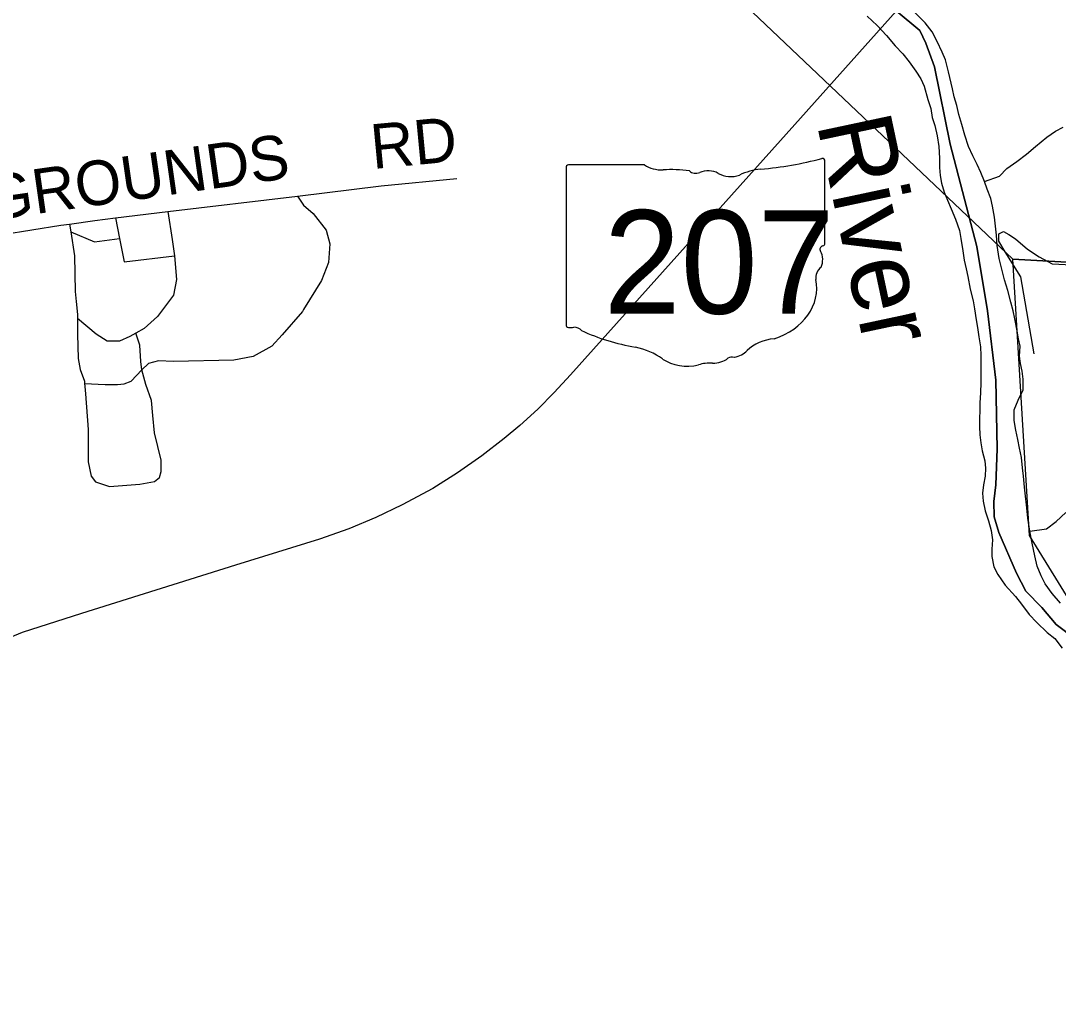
# Model space of a CAD drawing. Extents: x 0 to 34, y 0 to 22.
# Drawn here: x 3.839 to 5.16, y 18.553 to 19.8 of the extents above; entities that cross this region are included whole.
import ezdxf

# ---------------------------------------------------------------- set-up
doc = ezdxf.new("R2010")
doc.units = 0
for name, color, linetype in [('GM_X_Corporation', 7, 'Continuous'), ('GM_X_County_Road', 7, 'Continuous'), ('GM_X_County_Road_Text', 7, 'Continuous'), ('GM_X_Major_River', 7, 'Continuous'), ('GM_X_Major_River_Text', 7, 'Continuous'), ('GM_X_Minor_River', 7, 'Continuous'), ('GM_X_State_Location', 7, 'Continuous'), ('GM_X_State_Route', 7, 'Continuous'), ('GM_X_State_Shield', 7, 'Continuous'), ('GM_X_Township_Road', 7, 'Continuous'), ('SH_Data', 7, 'Continuous')]:
    doc.layers.add(name, color=color, linetype=linetype)

msp = doc.modelspace()

# ---------------------------------------------------------------- linework, layer by layer
at = {"layer": 'GM_X_Corporation'}
for points in [[(4.8161, 20.4698), (5.8125, 20.4147), (5.7537, 19.4608), (5.102, 19.4969), (4.7709, 19.8114)], [(5.102, 19.4969), (5.7537, 19.4608), (5.6796, 18.4816), (5.1903, 18.5084), (5.3139, 18.6644), (5.3147, 18.8352), (5.3148, 18.8557), (5.2004, 19.0195), (5.1234, 19.1449)]]:
    msp.add_lwpolyline(points, close=True, dxfattribs=at)
for points in [[(5.1813, 19.0133), (5.1572, 19.0317), (5.1391, 19.0531), (5.1188, 19.0738), (5.1068, 19.0967), (5.0844, 19.1486), (5.0785, 19.1684), (5.0779, 19.1882), (5.0804, 19.2095), (5.0822, 19.2551), (5.0807, 19.3425), (5.07, 19.4308), (5.0562, 19.513), (5.0223, 19.6432), (5.0025, 19.7419), (4.9914, 19.7718), (4.9836, 19.7878), (4.9535, 19.8132)], [(4.9535, 19.8132), (4.9836, 19.7878), (4.9914, 19.7718), (5.0025, 19.7419), (5.0223, 19.6432), (5.0562, 19.513), (5.07, 19.4308), (5.0807, 19.3425), (5.0822, 19.2551), (5.0804, 19.2095), (5.0779, 19.1882), (5.0785, 19.1684), (5.0844, 19.1486), (5.1068, 19.0967), (5.1188, 19.0738), (5.1391, 19.0531), (5.1572, 19.0317), (5.1813, 19.0133)]]:
    msp.add_lwpolyline(points, dxfattribs=at)
at = {"layer": 'GM_X_County_Road'}
for points in [[(4.1914, 19.5772), (4.2981, 19.5901), (4.3942, 19.5993)], [(3.5575, 19.4864), (3.89, 19.5399), (3.9012, 19.5415), (3.9335, 19.5461), (3.9596, 19.5492), (4.0263, 19.5573), (4.1914, 19.5772)], [(4.1914, 19.5772), (4.199, 19.5656), (4.2114, 19.5549), (4.2281, 19.5336), (4.2326, 19.5163), (4.2309, 19.4927), (4.2222, 19.4698), (4.1993, 19.4327)], [(4.0263, 19.5573), (4.0317, 19.5219), (4.0348, 19.5011), (4.0376, 19.4709), (4.0337, 19.4511), (4.0133, 19.4239), (3.9961, 19.4085), (3.9856, 19.4025), (3.9781, 19.3982), (3.9648, 19.3923), (3.9491, 19.3923), (3.935, 19.4011), (3.9115, 19.4212)], [(3.9596, 19.5492), (3.9647, 19.5231), (3.9706, 19.4934), (4.0348, 19.5011)], [(3.9012, 19.5415), (3.9027, 19.5317), (3.9076, 19.5011), (3.9084, 19.4555), (3.9097, 19.4428)], [(3.9027, 19.5317), (3.9329, 19.5188), (3.9647, 19.5231)], [(3.9097, 19.4428), (3.9115, 19.4261), (3.9115, 19.4212), (3.9115, 19.4011), (3.9123, 19.3703), (3.9146, 19.3563), (3.9201, 19.3416), (3.9204, 19.3386), (3.9208, 19.3348)], [(4.1993, 19.4327), (4.1987, 19.4319), (4.1977, 19.4302), (4.1718, 19.4005), (4.1588, 19.3858), (4.1349, 19.3728), (4.1103, 19.3681), (4.0335, 19.3665), (4.0145, 19.3672), (4.0017, 19.3639), (3.9931, 19.3558)], [(3.9208, 19.3348), (3.9217, 19.3254), (3.9248, 19.2799), (3.9248, 19.2387), (3.9287, 19.2204), (3.9342, 19.213), (3.9522, 19.2071), (3.9906, 19.2101), (4.0094, 19.2137), (4.0157, 19.2189), (4.018, 19.2262), (4.018, 19.2409), (4.0094, 19.2755), (4.0071, 19.2975), (4.0055, 19.3166), (3.9985, 19.3372), (3.9931, 19.3558), (3.9922, 19.3666), (3.9906, 19.3872), (3.9856, 19.4025)], [(3.9204, 19.3386), (3.9467, 19.3372), (3.9624, 19.3372), (3.971, 19.3379), (3.9797, 19.3416), (3.9931, 19.3558)]]:
    msp.add_lwpolyline(points, dxfattribs=at)
at = {"layer": 'GM_X_Major_River'}
for points in [[(4.9165, 19.8064), (4.9294, 19.7942), (4.9412, 19.7817), (4.9522, 19.7684), (4.962, 19.7581), (4.97, 19.7482), (4.9787, 19.736), (4.9851, 19.7265), (4.9893, 19.717), (4.9938, 19.6999), (4.9976, 19.6885), (4.9995, 19.6771), (5.0029, 19.6668), (5.0059, 19.6539), (5.0078, 19.6402), (5.0089, 19.6254), (5.0089, 19.6136), (5.0096, 19.6033), (5.0115, 19.5934), (5.0149, 19.582), (5.0191, 19.5718), (5.0236, 19.5607), (5.0293, 19.5478), (5.0342, 19.5334), (5.0361, 19.5231), (5.0383, 19.5075), (5.0402, 19.4953), (5.0428, 19.4843), (5.0447, 19.4748), (5.0477, 19.4585), (5.0515, 19.4436), (5.0534, 19.4334), (5.0556, 19.4197), (5.0572, 19.4098), (5.059, 19.3977), (5.0609, 19.3851), (5.0613, 19.3741), (5.0616, 19.3634), (5.0616, 19.3509), (5.0612, 19.3395), (5.0608, 19.3266), (5.06, 19.3137)], [(5.114, 19.3542), (5.1118, 19.3637), (5.1106, 19.3732), (5.1114, 19.3858), (5.1095, 19.3953), (5.1077, 19.4055), (5.1046, 19.4208), (5.1024, 19.431), (5.0997, 19.442), (5.0956, 19.4569), (5.0914, 19.4706), (5.088, 19.4839), (5.0846, 19.4975), (5.0824, 19.5143), (5.0813, 19.5272), (5.0802, 19.5386), (5.0787, 19.5504), (5.0764, 19.5641), (5.0741, 19.5739), (5.0696, 19.5861), (5.0662, 19.5956), (5.0613, 19.607), (5.0567, 19.6173), (5.0514, 19.6283), (5.0458, 19.6401), (5.0409, 19.6546), (5.0371, 19.6683), (5.0333, 19.6808), (5.0307, 19.6926), (5.0276, 19.7036), (5.0254, 19.7135), (5.0201, 19.7355), (5.0163, 19.7508), (5.0122, 19.7603), (5.0057, 19.774), (4.9993, 19.7865), (4.9906, 19.7979), (4.9766, 19.8116)], [(5.1629, 19.0585), (5.1523, 19.0711), (5.1432, 19.0832), (5.1383, 19.0935), (5.133, 19.1057), (5.13, 19.119), (5.1269, 19.1349), (5.1239, 19.1502), (5.1213, 19.1669), (5.1194, 19.184), (5.1183, 19.195), (5.1168, 19.2064), (5.1157, 19.2205), (5.1146, 19.2311), (5.1131, 19.244), (5.1108, 19.2562), (5.1086, 19.2672), (5.1059, 19.279), (5.104, 19.2912), (5.1037, 19.3049), (5.109, 19.3174), (5.1155, 19.3303), (5.1155, 19.344), (5.114, 19.3542)], [(5.06, 19.3137), (5.06, 19.3042), (5.0596, 19.2939), (5.0596, 19.2836), (5.06, 19.273), (5.0615, 19.2627), (5.0633, 19.2525), (5.0664, 19.2399), (5.0675, 19.2304), (5.0671, 19.2206), (5.0648, 19.2092), (5.0636, 19.1989), (5.0644, 19.1886), (5.067, 19.1761), (5.0712, 19.1635), (5.0746, 19.1514), (5.0764, 19.1392), (5.0753, 19.1274), (5.0753, 19.1179), (5.0779, 19.105), (5.0832, 19.0951), (5.0923, 19.0814), (5.1056, 19.067), (5.1131, 19.0574), (5.123, 19.0441), (5.1325, 19.0339), (5.1457, 19.0213), (5.1556, 19.0137), (5.1651, 19.0015)]]:
    msp.add_lwpolyline(points, dxfattribs=at)
at = {"layer": 'GM_X_Minor_River'}
for points in [[(5.0662, 19.5956), (5.0852, 19.6024), (5.0943, 19.6123), (5.1073, 19.621), (5.1194, 19.6305), (5.1312, 19.6404), (5.1453, 19.6521), (5.1563, 19.6597), (5.1662, 19.665)], [(5.1239, 19.1502), (5.1448, 19.1535), (5.1574, 19.1626), (5.1695, 19.174)]]:
    msp.add_lwpolyline(points, dxfattribs=at)
at = {"layer": 'GM_X_State_Route'}
for points in [[(4.9843, 19.8469), (4.9537, 19.8127), (4.8244, 19.6683)], [(4.8244, 19.6683), (4.5392, 19.3496), (4.5182, 19.3268), (4.4976, 19.3059), (4.4745, 19.2848), (4.4544, 19.2684), (4.4263, 19.2464), (4.3952, 19.2247), (4.3638, 19.2049), (4.3247, 19.1837), (4.2913, 19.1678), (4.2568, 19.1533), (4.2195, 19.1403), (4.1126, 19.1069), (3.9165, 19.0455), (3.8411, 19.0212), (3.7999, 19.0044), (3.7716, 18.9862), (3.7568, 18.9738)]]:
    msp.add_lwpolyline(points, dxfattribs=at)
at = {"layer": 'GM_X_State_Shield'}
for p, q in [((4.6331, 19.6167), (4.5366, 19.6167)), ((4.863, 19.517), (4.863, 19.6217)), ((4.5334, 19.6133), (4.5334, 19.4132)), ((4.8629, 19.517), (4.863, 19.517))]:
    msp.add_line(p, q, dxfattribs=at)
for centre, major_axis, start_param, end_param in [((4.5371, 19.6137), (0.00382, 0), 1.712693, 3.28349), ((4.6561, 19.64), (0.037, 0), 4.042523, 4.731795), ((4.7456, 19.8896), (0.3495, 0), 4.814394, 5.042369), ((4.8593, 19.6221), (0.00367, 0), 6.141152, 7.989035), ((4.6684, 19.5044), (0.133, 0), 1.404758, 1.657858), ((4.6986, 19.6147), (0.0107, 0), 3.836095, 5.185415), ((4.7143, 19.5916), (0.0222, 0), 0.950623, 2.079405), ((4.7429, 19.6233), (0.0267, 0), 4.081561, 5.145723), ((4.7901, 19.5556), (0.0703, 0), 1.699011, 2.107814), ((4.8621, 19.5093), (0.00568, 0), 1.883978, 3.671073), ((4.859, 19.5166), (0.00393, 0), 5.05454, 6.418171), ((4.826, 19.4961), (0.0341, 0), 5.934695, 6.695948), ((4.8761, 19.4732), (0.0248, 0), 2.387724, 3.262537), ((4.7651, 19.4599), (0.0874, 0), 5.101752, 6.440018), ((4.5372, 19.4127), (0.00385, 0), 3.00124, 4.508301), ((4.5378, 19.4332), (0.0294, 0), 4.665946, 4.897461), ((4.5438, 19.4016), (0.0106, 0), 0.519207, 1.627899), ((4.6776, 19.5814), (0.2524, 0), 4.195997, 4.488961), ((4.802, 19.357), (0.0479, 0), 1.647645, 2.488434), ((4.6024, 19.3233), (0.079, 0), 0.823519, 1.323587), ((4.7413, 19.3938), (0.0282, 0), 4.937069, 5.64225), ((4.6878, 19.4006), (0.0501, 0), 4.026481, 4.996735), ((4.7167, 19.3314), (0.0412, 0), 1.495662, 1.94098), ((4.7204, 19.3856), (0.0267, 0), 4.691044, 5.507374), ((4.7445, 19.3662), (0.00752, 0), 1.147584, 2.315152)]:
    msp.add_ellipse(centre, major_axis=major_axis, ratio=0.8, start_param=start_param, end_param=end_param, dxfattribs=at)
at = {"layer": 'GM_X_Township_Road'}
for points in [[(5.1295, 19.3763), (5.1124, 19.4743), (5.0923, 19.5061), (5.0844, 19.5199), (5.0842, 19.5289), (5.0902, 19.532), (5.0969, 19.5282)], [(5.0969, 19.5282), (5.1057, 19.5228), (5.1208, 19.5094), (5.1358, 19.4998), (5.1521, 19.491), (5.2023, 19.4881), (5.4979, 19.4701)]]:
    msp.add_lwpolyline(points, dxfattribs=at)
at = {"layer": 'SH_Data'}
for p, q in [((4.6331, 19.6167), (4.5366, 19.6167)), ((4.863, 19.517), (4.863, 19.6217)), ((4.5334, 19.6133), (4.5334, 19.4132)), ((4.8629, 19.517), (4.863, 19.517))]:
    msp.add_line(p, q, dxfattribs=at)
for centre, major_axis, start_param, end_param in [((4.5371, 19.6137), (0.00382, 0), 1.712693, 3.28349), ((4.6561, 19.64), (0.037, 0), 4.042523, 4.731795), ((4.7456, 19.8896), (0.3495, 0), 4.814394, 5.042369), ((4.8593, 19.6221), (0.00367, 0), 6.141152, 7.989035), ((4.6684, 19.5044), (0.133, 0), 1.404758, 1.657858), ((4.6986, 19.6147), (0.0107, 0), 3.836095, 5.185415), ((4.7143, 19.5916), (0.0222, 0), 0.950623, 2.079405), ((4.7429, 19.6233), (0.0267, 0), 4.081561, 5.145723), ((4.7901, 19.5556), (0.0703, 0), 1.699011, 2.107814), ((4.8621, 19.5093), (0.00568, 0), 1.883978, 3.671073), ((4.859, 19.5166), (0.00393, 0), 5.05454, 6.418171), ((4.826, 19.4961), (0.0341, 0), 5.934695, 6.695948), ((4.8761, 19.4732), (0.0248, 0), 2.387724, 3.262537), ((4.7651, 19.4599), (0.0874, 0), 5.101752, 6.440018), ((4.5372, 19.4127), (0.00385, 0), 3.00124, 4.508301), ((4.5378, 19.4332), (0.0294, 0), 4.665946, 4.897461), ((4.5438, 19.4016), (0.0106, 0), 0.519207, 1.627899), ((4.6776, 19.5814), (0.2524, 0), 4.195997, 4.488961), ((4.802, 19.357), (0.0479, 0), 1.647645, 2.488434), ((4.6024, 19.3233), (0.079, 0), 0.823519, 1.323587), ((4.7413, 19.3938), (0.0282, 0), 4.937069, 5.64225), ((4.6878, 19.4006), (0.0501, 0), 4.026481, 4.996735), ((4.7167, 19.3314), (0.0412, 0), 1.495662, 1.94098), ((4.7204, 19.3856), (0.0267, 0), 4.691044, 5.507374), ((4.7445, 19.3662), (0.00752, 0), 1.147584, 2.315152)]:
    msp.add_ellipse(centre, major_axis=major_axis, ratio=0.8, start_param=start_param, end_param=end_param, dxfattribs=at)

# ---------------------------------------------------------------- texts
at = {"layer": 'GM_X_County_Road_Text'}
for s, height, rotation, p in [('RD', 0.05682, 5.4156, (4.2873, 19.6115)), ('FAIRGROUNDS', 0.056818, 8.1161, (3.628, 19.5213))]:
    msp.add_text(s, height=height, rotation=rotation, dxfattribs=at).set_placement(p)
at = {"layer": 'GM_X_Major_River_Text'}
msp.add_text('River', height=0.0947, rotation=281.998, dxfattribs=at).set_placement((4.8523, 19.67))
at = {"layer": 'GM_X_State_Location'}
for s, p in [('s', (4.6945, 19.4999)), ('r', (4.6944, 19.4999))]:
    msp.add_text(s, height=0.000189, dxfattribs=at).set_placement(p)
msp.add_text('207', height=0.000189, rotation=0, dxfattribs=at).set_placement((4.6276, 19.4861))
at = {"layer": 'GM_X_State_Shield'}
msp.add_text('207', height=0.13184, dxfattribs=at).set_placement((4.5812, 19.4273))
at = {"layer": 'SH_Data'}
msp.add_text('207', height=0.13184, dxfattribs=at).set_placement((4.5812, 19.4273))

doc.saveas('drawing.dxf')
